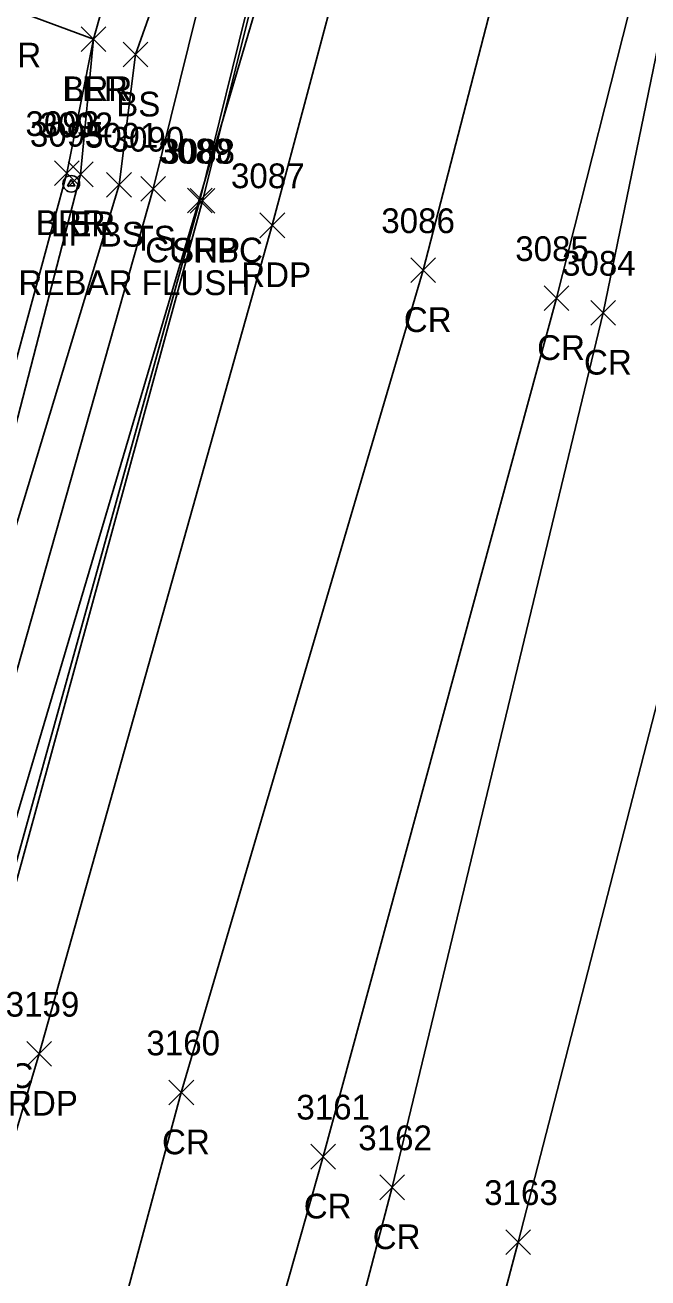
# Model space of a CAD drawing. Extents: x 1462089 to 1464015, y 730534 to 736144.
# Drawn here: x 1463088.7 to 1463139, y 733083.4 to 733184.7 of the extents above; entities that cross this region are included whole.
import ezdxf

# ---------------------------------------------------------------- set-up
doc = ezdxf.new("R2010")
doc.units = 0
for name, color, linetype in [('DCP', 7, 'Continuous'), ('L_A', 7, 'Continuous'), ('L_I', 7, 'Continuous'), ('L_TIC', 7, 'Continuous'), ('LABL', 7, 'Continuous'), ('LARO', 7, 'Continuous'), ('LELB', 7, 'Continuous'), ('M_A', 7, 'Continuous'), ('M_C', 7, 'Continuous'), ('M_I', 7, 'Continuous'), ('MPIR', 7, 'Continuous'), ('P_A', 7, 'Continuous'), ('P_I', 7, 'Continuous'), ('P_TIC', 7, 'Continuous'), ('PET', 7, 'Continuous'), ('PRC', 7, 'Continuous'), ('PSP', 7, 'Continuous'), ('R_A', 7, 'Continuous'), ('R_I', 7, 'Continuous'), ('R_TIC', 7, 'Continuous'), ('RC', 7, 'Continuous')]:
    doc.layers.add(name, color=color, linetype=linetype)

msp = doc.modelspace()

# ---------------------------------------------------------------- linework, layer by layer
at = {"layer": 'DCP'}
msp.add_lwpolyline([(1463113.91, 733208.21), (1463020.77, 732893.28)], dxfattribs=at)
at = {"layer": 'L_TIC'}
for points in [[(1463093.26, 733182.58), (1463095.26, 733184.58)], [(1463095.26, 733182.58), (1463093.26, 733184.58)], [(1463093.26, 733182.58), (1463095.26, 733184.58)], [(1463095.26, 733182.58), (1463093.26, 733184.58)], [(1463096.65, 733181.34), (1463098.65, 733183.34)], [(1463098.65, 733181.34), (1463096.65, 733183.34)], [(1463091.11, 733171.76), (1463093.11, 733173.76)], [(1463093.11, 733171.76), (1463091.11, 733173.76)], [(1463092.23, 733171.66), (1463094.23, 733173.66)], [(1463094.23, 733171.66), (1463092.23, 733173.66)], [(1463095.33, 733170.82), (1463097.33, 733172.82)], [(1463097.33, 733170.82), (1463095.33, 733172.82)], [(1463098.08, 733170.5), (1463100.08, 733172.5)], [(1463100.08, 733170.5), (1463098.08, 733172.5)]]:
    msp.add_lwpolyline(points, dxfattribs=at)
at = {"layer": 'LABL'}
msp.add_lwpolyline([(1463052.45, 733194.5), (1463067.07, 733192.93), (1463078.58, 733189.91), (1463086.91, 733186.3), (1463094.26, 733183.58), (1463092.11, 733172.76), (1463083.33, 733140.42), (1463080.34, 733131.51), (1463076.28, 733126.39), (1463067.39, 733109.86), (1463045.39, 733071.47), (1463024.96, 733052.89)], dxfattribs=at)
at = {"layer": 'LARO'}
msp.add_lwpolyline([(1463094.76, 733228.15), (1463096.03, 733229.51), (1463107.11, 733225.67), (1463106.44, 733220.79), (1463101.84, 733210.57), (1463094.26, 733183.58), (1463093.23, 733172.66), (1463084.96, 733140.71), (1463082.5, 733130.85), (1463075.1, 733107.4), (1463060.71, 733062.18), (1463041.43, 733003.63), (1463027.29, 732956.25), (1463020.7, 732939.68), (1463009.72, 732922.59), (1463000.8, 732913.83)], dxfattribs=at)
at = {"layer": 'LELB'}
for points in [[(1463108.71, 733226.1), (1463108.78, 733215.45), (1463107.91, 733210.67), (1463106.52, 733207.37), (1463097.65, 733182.34), (1463096.33, 733171.82), (1463062.97, 733061.46), (1463044.31, 733003.12), (1463029.33, 732955.28), (1463018.11, 732921.02), (1463012.52, 732895.45), (1463002.14, 732868.56), (1462989.94, 732828.37), (1462974.14, 732778.17), (1462962.05, 732738.86), (1462942.09, 732684.7)], [(1463108.71, 733226.1), (1463110.44, 733215.45), (1463109.61, 733208.14), (1463106.26, 733200.46), (1463099.08, 733171.5), (1463080.2, 733104.81), (1463066.07, 733061.12), (1463047.44, 733002.3), (1463031.89, 732954.26), (1463021.29, 732920.45), (1463016.04, 732893.81), (1463006.16, 732867.27), (1462993.39, 732826.96), (1462975.9, 732776.47), (1462964.59, 732738.3), (1462945.3, 732683.44)]]:
    msp.add_lwpolyline(points, dxfattribs=at)
at = {"layer": 'MPIR'}
msp.add_lwpolyline([(1463092.47, 733172.24), (1463092.18, 733171.74), (1463092.76, 733171.74)], close=True, dxfattribs=at)
msp.add_circle((1463092.47, 733171.9), 0.667, dxfattribs=at)
at = {"layer": 'P_TIC'}
for points in [[(1463102.08, 733169.52), (1463104.08, 733171.52)], [(1463104.08, 733169.52), (1463102.08, 733171.52)], [(1463107.71, 733167.54), (1463109.71, 733169.54)], [(1463109.71, 733167.54), (1463107.71, 733169.54)], [(1463119.9, 733163.91), (1463121.9, 733165.91)], [(1463121.9, 733163.91), (1463119.9, 733165.91)], [(1463130.67, 733161.65), (1463132.67, 733163.65)], [(1463132.67, 733161.65), (1463130.67, 733163.65)], [(1463134.44, 733160.47), (1463136.44, 733162.47)], [(1463136.44, 733160.47), (1463134.44, 733162.47)], [(1463088.87, 733100.56), (1463090.87, 733102.56)], [(1463090.87, 733100.56), (1463088.87, 733102.56)], [(1463100.36, 733097.43), (1463102.36, 733099.43)], [(1463102.36, 733097.43), (1463100.36, 733099.43)], [(1463111.82, 733092.24), (1463113.82, 733094.24)], [(1463113.82, 733092.24), (1463111.82, 733094.24)], [(1463117.39, 733089.76), (1463119.39, 733091.76)], [(1463119.39, 733089.76), (1463117.39, 733091.76)], [(1463127.56, 733085.33), (1463129.56, 733087.33)], [(1463129.56, 733085.33), (1463127.56, 733087.33)]]:
    msp.add_lwpolyline(points, dxfattribs=at)
at = {"layer": 'PET'}
msp.add_lwpolyline([(1463162.64, 733438.25), (1463155.29, 733389.19), (1463147.91, 733342.63), (1463141.51, 733306.47), (1463132.06, 733260.3), (1463123.36, 733223.56), (1463108.71, 733168.54), (1463089.87, 733101.56), (1463076.27, 733055.88), (1463056.85, 732997.04), (1463043.72, 732952), (1463030.35, 732910.94), (1463015.8, 732864.49), (1463002.53, 732823.32), (1462986.53, 732773.32), (1462974.36, 732735), (1462957.21, 732680.82)], dxfattribs=at)
at = {"layer": 'PRC'}
for points in [[(1463173.05, 733431.97), (1463166.54, 733387.93), (1463158.95, 733340.73), (1463152.26, 733304.55), (1463143.59, 733257.28), (1463135.29, 733220.7), (1463120.9, 733164.91), (1463101.36, 733098.43), (1463088.62, 733051.16), (1463070, 732996.41), (1463055.29, 732948.06), (1463043.07, 732909.01), (1463027.36, 732860.42), (1463013.91, 732819.27), (1462999.18, 732769.26), (1462985.72, 732731.93), (1462969.44, 732677.27)], [(1463184.26, 733428.99), (1463177.5, 733386.21), (1463169.42, 733335), (1463162.87, 733301.13), (1463154.54, 733254.52), (1463145.29, 733216.48), (1463131.67, 733162.65), (1463112.82, 733093.24), (1463099.08, 733044.74), (1463082.5, 732993.09), (1463066.93, 732944.79), (1463054.22, 732905.14), (1463038.5, 732856.13), (1463025.08, 732814.55), (1463009.9, 732766.25), (1462997.49, 732727.73), (1462980.34, 732670.55), (1462968.82, 732637.25), (1462956.14, 732592.49), (1462943.23, 732555.63), (1462933.85, 732526.13), (1462921.41, 732485.16), (1462905.69, 732440.94), (1462895.98, 732404.53)], [(1463173.56, 733299.02), (1463165.51, 733252.57), (1463157.36, 733210.85), (1463147.48, 733159.84), (1463128.56, 733086.33), (1463116.13, 733039.22), (1463100.45, 732983.58), (1463087.95, 732938.84), (1463073.8, 732896.76), (1463059.6, 732849.78), (1463047.56, 732806.21), (1463032.36, 732758.17), (1463016.83, 732714.7), (1463001.87, 732663.36), (1462991.08, 732629.32), (1462977.35, 732584.7), (1462966.06, 732548.54), (1462956.48, 732518.6), (1462941.54, 732474.04), (1462928.1, 732429.75), (1462916.12, 732396.98)], [(1463154.54, 733254.52), (1463146.61, 733215.85), (1463135.44, 733161.47), (1463118.39, 733090.76), (1463105.83, 733042.87), (1463089.37, 732989.24), (1463076.43, 732943.44), (1463063.88, 732901.54), (1463049.78, 732852.76), (1463036.58, 732810.58), (1463021.66, 732763.56), (1463007.35, 732718.7), (1462991.11, 732667.44), (1462980.42, 732633.72), (1462966.43, 732588.15), (1462955.05, 732551.99), (1462945.51, 732521.94), (1462931.54, 732478.17), (1462917.14, 732435.42), (1462906.01, 732400.46)]]:
    msp.add_lwpolyline(points, dxfattribs=at)
at = {"layer": 'PSP'}
msp.add_lwpolyline([(1463155.47, 733437.1), (1463151.69, 733409.08), (1463149, 733391.93), (1463141.96, 733349.08), (1463135.18, 733308.49), (1463125.93, 733264.09), (1463122.72, 733251.49), (1463119.11, 733234.45), (1463113.24, 733211.25), (1463103.08, 733170.52), (1463084.78, 733103.69), (1463070.66, 733057.94), (1463052.86, 733000.45), (1463038.28, 732952.98), (1463025.31, 732912.14), (1463010.74, 732866.35), (1462997.43, 732825.46), (1462981.2, 732774.91), (1462968.73, 732736.5), (1462951.61, 732681.88)], dxfattribs=at)
at = {"layer": 'R_TIC'}
for points in [[(1463101.86, 733169.54), (1463103.86, 733171.54)], [(1463103.86, 733169.54), (1463101.86, 733171.54)]]:
    msp.add_lwpolyline(points, dxfattribs=at)
at = {"layer": 'RC'}
msp.add_lwpolyline([(1463111.2, 733221.62), (1463111.65, 733221.54), (1463112.56, 733218.83), (1463113.16, 733213.96), (1463112.93, 733211.4), (1463102.86, 733170.54), (1463084.32, 733103.79), (1463070.5, 733057.91), (1463052.69, 733000.48), (1463038.08, 732953.17), (1463025.2, 732912.25), (1463010.5, 732866.43), (1462997.21, 732825.5), (1462981.06, 732775.17), (1462968.5, 732736.53), (1462951.35, 732681.84)], dxfattribs=at)

# ---------------------------------------------------------------- texts
at = {"layer": 'L_A'}
for s, p in [('BRR', (1463084.4, 733181.3)), ('BRR', (1463091.75, 733178.58)), ('LER', (1463091.84, 733178.58)), ('BS', (1463096.1, 733177.34)), ('BRR', (1463089.6, 733167.76)), ('LER', (1463090.82, 733167.66)), ('BS', (1463094.77, 733166.82)), ('TS', (1463097.49, 733166.5))]:
    msp.add_text(s, height=2, dxfattribs=at).set_placement(p)
at = {"layer": 'L_I'}
for s, p in [('3093', (1463088.77, 733175.76)), ('3092', (1463089.9, 733175.66)), ('3091', (1463093.56, 733174.82)), ('3090', (1463095.65, 733174.5))]:
    msp.add_text(s, height=2, dxfattribs=at).set_placement(p)
at = {"layer": 'M_A'}
msp.add_text('IP', height=2, dxfattribs=at).set_placement((1463091.52, 733166.9))
at = {"layer": 'M_C'}
msp.add_text('RLS 565 1" REBAR FLUSH', height=2, dxfattribs=at).set_placement((1463073.87, 733162.9))
at = {"layer": 'M_I'}
msp.add_text('3095', height=2, dxfattribs=at).set_placement((1463089.13, 733174.9))
at = {"layer": 'P_A'}
for s, p in [('SHP', (1463100.61, 733165.52)), ('RDP', (1463106.2, 733163.54)), ('CR', (1463119.33, 733159.91)), ('CR', (1463130.1, 733157.65)), ('CR', (1463133.88, 733156.47)), ('RDP', (1463087.36, 733096.56)), ('CR', (1463099.8, 733093.43)), ('CR', (1463111.25, 733088.24)), ('CR', (1463116.82, 733085.76))]:
    msp.add_text(s, height=2, dxfattribs=at).set_placement(p)
at = {"layer": 'P_I'}
for s, p in [('3088', (1463099.74, 733173.52)), ('3087', (1463105.37, 733171.54)), ('3086', (1463117.51, 733167.91)), ('3085', (1463128.33, 733165.65)), ('3084', (1463132.11, 733164.47)), ('3159', (1463087.17, 733104.56)), ('3160', (1463098.54, 733101.43)), ('3161', (1463110.65, 733096.24)), ('3162', (1463115.65, 733093.76)), ('3163', (1463125.82, 733089.33))]:
    msp.add_text(s, height=2, dxfattribs=at).set_placement(p)
at = {"layer": 'R_A'}
for p in [(1463098.44, 733165.54), (1463079.9, 733098.79)]:
    msp.add_text('CURBC', height=2, dxfattribs=at).set_placement(p)
at = {"layer": 'R_I'}
msp.add_text('3089', height=2, dxfattribs=at).set_placement((1463099.51, 733173.54))

doc.saveas('drawing.dxf')
